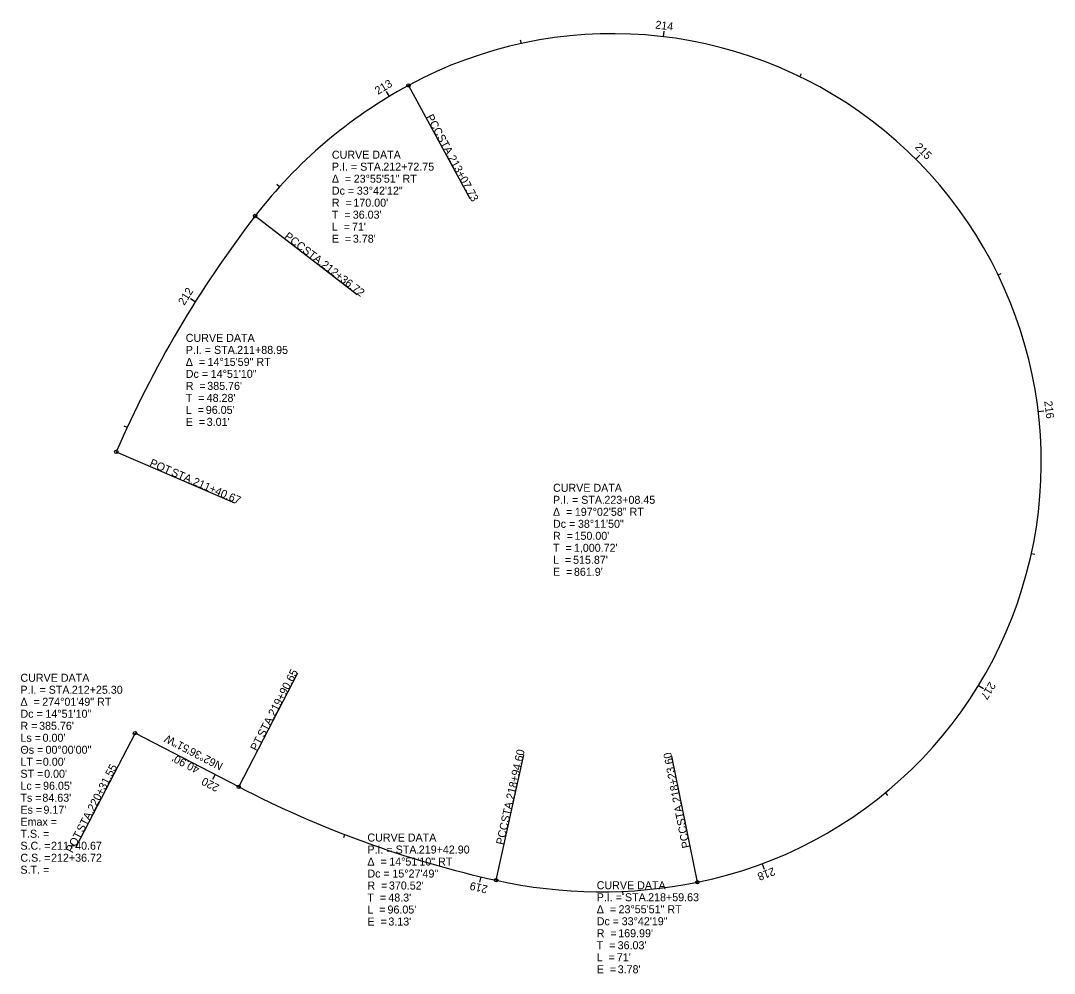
# Model space of a CAD drawing. Extents: x 186365 to 186727, y 352537 to 352871.
import ezdxf

# ---------------------------------------------------------------- set-up
doc = ezdxf.new("R2010")
doc.units = 0
for name, color, linetype in [('GE_X_Alignment', 7, 'Continuous'), ('GE_X_Alignment_100_Bearings', 7, 'Continuous'), ('GE_X_Alignment_100_Cardinal_Points', 7, 'Continuous'), ('GE_X_Alignment_100_Curve_Data', 7, 'Continuous'), ('GE_X_Alignment_100_Distances', 7, 'Continuous'), ('GE_X_Alignment_100_Stations', 7, 'Continuous')]:
    doc.layers.add(name, color=color, linetype=linetype)

msp = doc.modelspace()

# ---------------------------------------------------------------- linework, layer by layer
at = {"layer": 'GE_X_Alignment'}
msp.add_line((186441.38, 352602.49), (186405.06, 352621.3), dxfattribs=at)
for centre, radius, start, end in [((186572.24, 352716.14), 150, 281.3976, 118.4471), ((186581.77, 352698.55), 170, 118.4471, 142.3779), ((186752.67, 352566.84), 385.76, 142.3779, 156.6443), ((186611.81, 352931.48), 370.52, 242.614, 257.4668), ((186568.29, 352735.73), 169.99, 257.4668, 281.3976)]:
    msp.add_arc(centre, radius, start, end, dxfattribs=at)
at = {"layer": 'GE_X_Alignment_100_Cardinal_Points'}
for p, q in [((186500.79, 352848.02), (186522.23, 352808.46)), ((186447.12, 352802.33), (186482.77, 352774.86)), ((186398.51, 352719.77), (186439.83, 352701.93)), ((186441.38, 352602.49), (186462.08, 352642.45)), ((186405.06, 352621.3), (186384.36, 352581.34)), ((186531.41, 352569.79), (186541.17, 352613.72)), ((186601.89, 352569.09), (186592.99, 352613.21))]:
    msp.add_line(p, q, dxfattribs=at)
for centre in [(186500.79, 352848.02), (186447.12, 352802.33), (186398.51, 352719.77), (186405.06, 352621.3), (186441.38, 352602.49), (186531.41, 352569.79), (186601.89, 352569.09)]:
    msp.add_circle(centre, 0.6, dxfattribs=at)
at = {"layer": 'GE_X_Alignment_100_Stations'}
for p, q in [((186590, 352865.08), (186590.24, 352867.07)), ((186540.29, 352862.69), (186540.03, 352863.87)), ((186637.76, 352851.07), (186638.28, 352852.15)), ((186494.08, 352844.19), (186493.05, 352845.9)), ((186678.3, 352822.21), (186679.72, 352823.63)), ((186455.63, 352812.52), (186454.74, 352813.32)), ((186707.17, 352781.67), (186708.25, 352782.2)), ((186426.12, 352772.22), (186424.43, 352773.28)), ((186721.19, 352733.92), (186723.17, 352734.15)), ((186402.32, 352728.29), (186401.23, 352728.79)), ((186718.81, 352684.21), (186719.98, 352683.95)), ((186700.29, 352638.01), (186702, 352636.97)), ((186433.08, 352606.79), (186432.16, 352605.01)), ((186667.68, 352600.41), (186668.44, 352599.49)), ((186478.43, 352585.8), (186478, 352584.69)), ((186624.56, 352575.56), (186625.26, 352573.68)), ((186526.15, 352571), (186525.68, 352569.06)), ((186575.71, 352565.9), (186575.76, 352564.71))]:
    msp.add_line(p, q, dxfattribs=at)

# ---------------------------------------------------------------- texts
at = {"layer": 'GE_X_Alignment_100_Bearings'}
msp.add_text('N62°36\'51"W', height=2.8, rotation=152.614, dxfattribs=at).set_placement((186436.11, 352610.62))
at = {"layer": 'GE_X_Alignment_100_Cardinal_Points'}
for s, rotation, p in [('PCC', 298.4471, (186506.8, 352837.01)), (' STA. ', 298.4471, (186510.12, 352830.88)), ('213+07.73', 298.4471, (186514.56, 352822.69)), ('PCC', 322.3779, (186457.08, 352794.7)), (' STA. ', 322.3779, (186462.59, 352790.45)), ('212+36.72', 322.3779, (186469.97, 352784.76)), ('POT', 336.6443, (186409.93, 352714.88)), (' STA. ', 336.6443, (186416.48, 352712.05)), ('211+40.67', 336.6443, (186425.04, 352708.36)), ('219+90.65', 62.614, (186454, 352626.94)), (' STA. ', 62.614, (186449.72, 352618.67)), ('PT', 62.614, (186447.72, 352614.8)), ('218+94.60', 77.4668, (186537.61, 352597.88)), ('218+23.60', 101.3976, (186596.17, 352597.29)), ('220+31.55', 62.614, (186390.73, 352593.71)), (' STA. ', 77.4668, (186535.59, 352588.78)), (' STA. ', 101.3976, (186598.01, 352588.15)), (' STA. ', 62.614, (186386.44, 352585.44)), ('PCC', 77.4668, (186534.08, 352581.99)), ('POT', 62.614, (186383.16, 352579.11)), ('PCC', 101.3976, (186599.38, 352581.32))]:
    msp.add_text(s, height=2.8, rotation=rotation, dxfattribs=at).set_placement(p)
at = {"layer": 'GE_X_Alignment_100_Curve_Data'}
for s, p in [('CURVE DATA', (186473.96, 352822.38)), ('P.I. = STA. ', (186473.96, 352818.18)), ('212+72.75', (186491.95, 352818.18)), ('Δ  = ', (186473.96, 352813.98)), ('23°55\'51" RT', (186481.6, 352813.98)), ('Dc = ', (186473.96, 352809.78)), ('33°42\'12"', (186482.7, 352809.78)), ('R  = ', (186473.96, 352805.58)), ("170.00'", (186481.49, 352805.58)), ('T  = ', (186473.96, 352801.38)), ("36.03'", (186481.28, 352801.38)), ('L  = ', (186473.96, 352797.18)), ("71'", (186480.99, 352797.18)), ('E  = ', (186473.96, 352792.98)), ("3.78'", (186481.3, 352792.98)), ('CURVE DATA', (186422.82, 352758.25)), ('P.I. = STA. ', (186422.82, 352754.05)), ('211+88.95', (186440.81, 352754.05)), ('Δ  = ', (186422.82, 352749.85)), ('14°15\'59" RT', (186430.46, 352749.85)), ('Dc = ', (186422.82, 352745.65)), ('14°51\'10"', (186431.56, 352745.65)), ('R  = ', (186422.82, 352741.45)), ("385.76'", (186430.35, 352741.45)), ('T  = ', (186422.82, 352737.25)), ("48.28'", (186430.14, 352737.25)), ('L  = ', (186422.82, 352733.05)), ("96.05'", (186429.85, 352733.05)), ('E  = ', (186422.82, 352728.85)), ("3.01'", (186430.16, 352728.85)), ('CURVE DATA', (186551.34, 352705.76)), ('P.I. = STA. ', (186551.34, 352701.56)), ('223+08.45', (186569.33, 352701.56)), ('Δ  = ', (186551.34, 352697.36)), ('197°02\'58" RT', (186558.99, 352697.36)), ('Dc = ', (186551.34, 352693.16)), ('38°11\'50"', (186560.08, 352693.16)), ('R  = ', (186551.34, 352688.96)), ("150.00'", (186558.88, 352688.96)), ('T  = ', (186551.34, 352684.76)), ("1,000.72'", (186558.66, 352684.76)), ('L  = ', (186551.34, 352680.56)), ("515.87'", (186558.38, 352680.56)), ('E  = ', (186551.34, 352676.36)), ("861.9'", (186558.68, 352676.36)), ('CURVE DATA', (186364.96, 352639.27)), ('P.I. = STA. ', (186364.96, 352635.07)), ('212+25.30', (186382.95, 352635.07)), ('Δ  = ', (186364.96, 352630.87)), ('274°01\'49" RT', (186372.61, 352630.87)), ('Dc = ', (186364.96, 352626.67)), ('14°51\'10"', (186373.71, 352626.67)), ('R = ', (186364.96, 352622.47)), ("385.76'", (186371.5, 352622.47)), ('Ls = ', (186364.96, 352618.27)), ("0.00'", (186372.71, 352618.27)), ('Θs = ', (186364.96, 352614.07)), ('00°00\'00"', (186373.75, 352614.07)), ('LT = ', (186364.96, 352609.87)), ("0.00'", (186372.81, 352609.87)), ('ST = ', (186364.96, 352605.67)), ("0.00'", (186373.26, 352605.67)), ('Lc = ', (186364.96, 352601.47)), ("96.05'", (186372.88, 352601.47)), ('Ts = ', (186364.96, 352597.27)), ("84.63'", (186372.65, 352597.27)), ('Es = ', (186364.96, 352593.07)), ("9.17'", (186373.02, 352593.07)), ('Emax = ', (186364.96, 352588.87)), ('T.S. = ', (186364.96, 352584.67)), ('CURVE DATA', (186486.39, 352583.34)), ('S.C. = ', (186364.96, 352580.47)), ('211+40.67', (186375.67, 352580.47)), ('C.S. = ', (186364.96, 352576.27)), ('212+36.72', (186375.67, 352576.27)), ('P.I. = STA. ', (186486.39, 352579.14)), ('219+42.90', (186504.38, 352579.14)), ('Δ  = ', (186486.39, 352574.94)), ('14°51\'10" RT', (186494.04, 352574.94)), ('S.T. = ', (186364.96, 352572.07)), ('Dc = ', (186486.39, 352570.74)), ('15°27\'49"', (186495.14, 352570.74)), ('R  = ', (186486.39, 352566.54)), ("370.52'", (186493.93, 352566.54)), ('CURVE DATA', (186566.65, 352566.64)), ('T  = ', (186486.39, 352562.34)), ("48.3'", (186493.71, 352562.34)), ('P.I. = STA. ', (186566.65, 352562.44)), ('218+59.63', (186584.64, 352562.44)), ('L  = ', (186486.39, 352558.14)), ("96.05'", (186493.43, 352558.14)), ('Δ  = ', (186566.65, 352558.24)), ('23°55\'51" RT', (186574.29, 352558.24)), ('E  = ', (186486.39, 352553.94)), ("3.13'", (186493.73, 352553.94)), ('Dc = ', (186566.65, 352554.04)), ('33°42\'19"', (186575.39, 352554.04)), ('R  = ', (186566.65, 352549.84)), ("169.99'", (186574.18, 352549.84)), ('T  = ', (186566.65, 352545.64)), ("36.03'", (186573.97, 352545.64)), ('L  = ', (186566.65, 352541.44)), ("71'", (186573.68, 352541.44)), ('E  = ', (186566.65, 352537.24)), ("3.78'", (186573.99, 352537.24))]:
    msp.add_text(s, height=2.8, dxfattribs=at).set_placement(p)
at = {"layer": 'GE_X_Alignment_100_Distances'}
msp.add_text("40.90'", height=2.8, rotation=152.614, dxfattribs=at).set_placement((186427.93, 352609.42))
at = {"layer": 'GE_X_Alignment_100_Stations'}
for s, rotation, p in [('214', 353.2021, (186587.04, 352867.95)), ('213', 31.052, (186490.05, 352844.68)), ('215', 315.0049, (186677.8, 352826.25)), ('212', 57.8325, (186422.3, 352770.83)), ('216', 276.8077, (186723.28, 352737.45)), ('217', 238.6105, (186704.12, 352639.47)), ('220', 152.614, (186434.83, 352603.06)), ('218', 200.4133, (186628.48, 352574.35)), ('219', 166.6323, (186528.71, 352567.82))]:
    msp.add_text(s, height=2.8, rotation=rotation, dxfattribs=at).set_placement(p)

doc.saveas('drawing.dxf')
